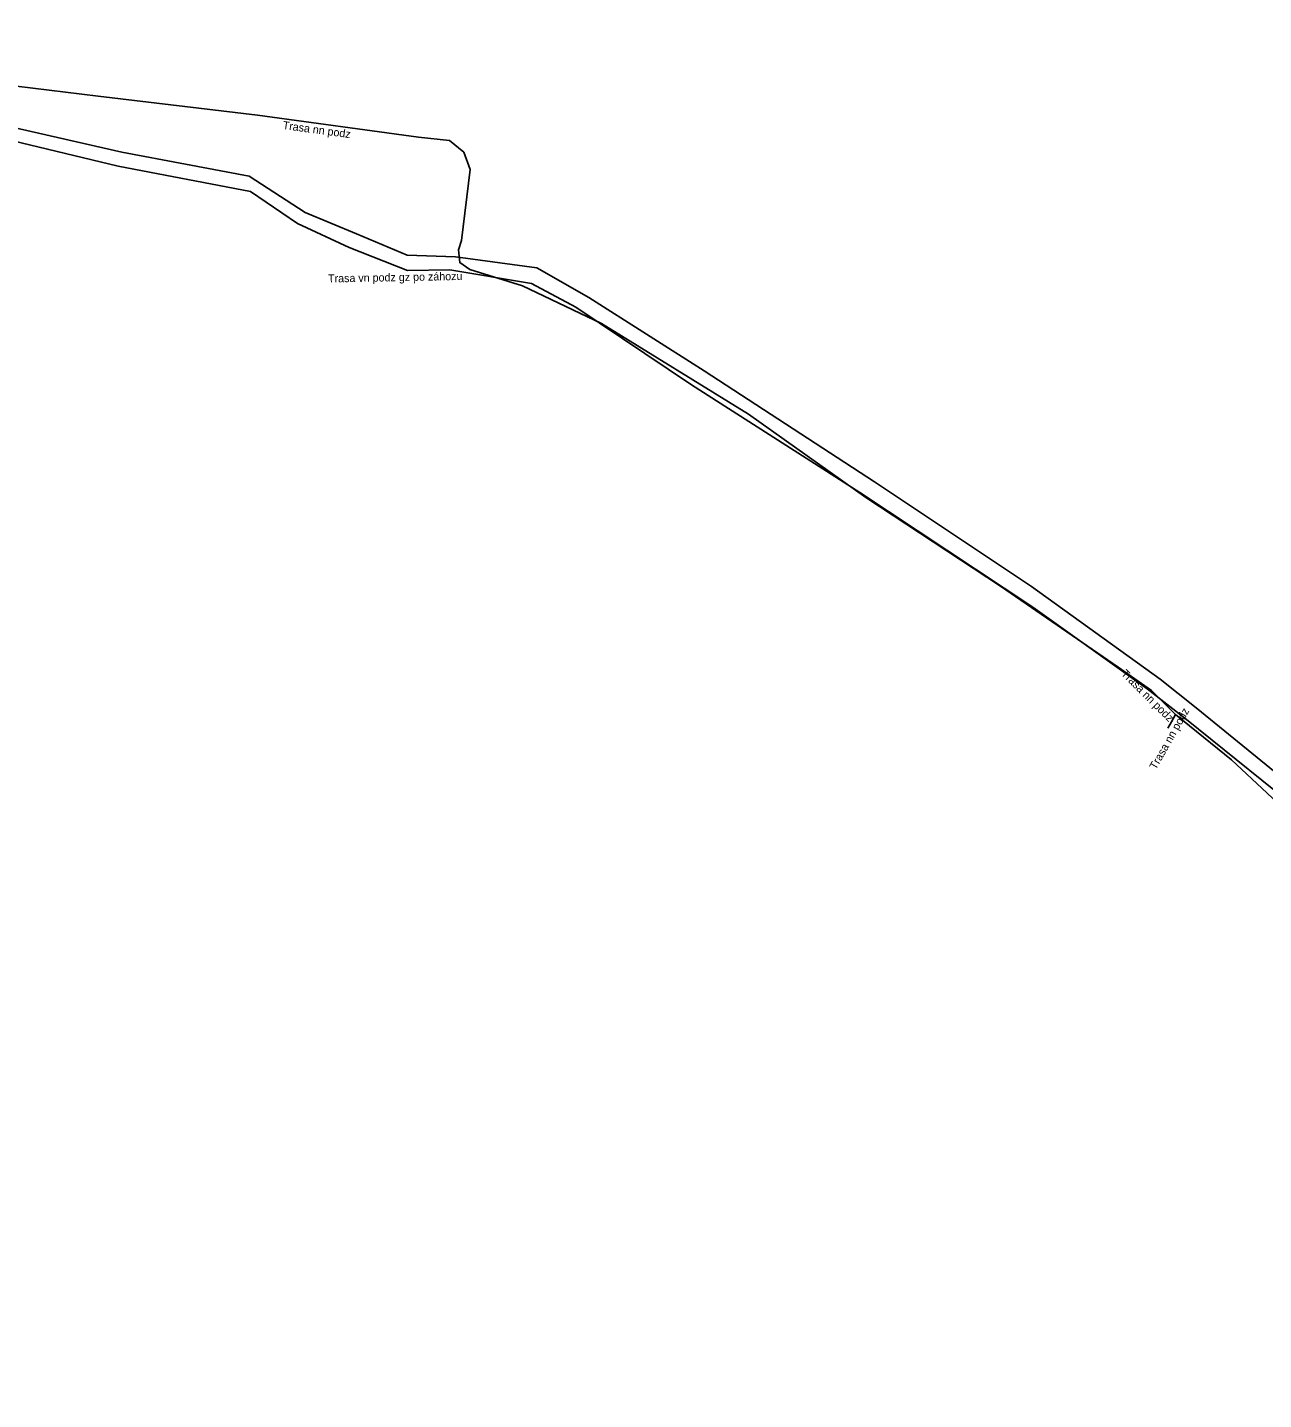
# Model space of a CAD drawing. Extents: x -651117 to -650186, y -983707 to -983198.
# Drawn here: x -650484.5 to -650407.2, y -983616.7 to -983530.9 of the extents above; entities that cross this region are included whole.
import ezdxf

# ---------------------------------------------------------------- set-up
doc = ezdxf.new("R2010")
doc.units = 0
for name, color, linetype in [('Popiskový text - Ostatní atributy Trasy', 7, 'Continuous'), ('Spojnice NN', 7, 'Continuous'), ('Spojnice VN', 7, 'Continuous')]:
    doc.layers.add(name, color=color, linetype=linetype)

msp = doc.modelspace()

# ---------------------------------------------------------------- linework, layer by layer
at = {"layer": 'Spojnice NN'}
for points in [[(-650490.27, -983533.98), (-650480.03, -983535.23), (-650470.09, -983536.41), (-650460.03, -983537.79), (-650458.09, -983538), (-650457.2, -983538.74), (-650456.8, -983539.82), (-650457.33, -983544.25), (-650457.52, -983544.84), (-650457.45, -983545.63), (-650456.81, -983546.06), (-650453.53, -983547.09), (-650448.59, -983549.43), (-650439.41, -983555.1), (-650432.08, -983560.3), (-650423.66, -983565.85), (-650416.32, -983570.9), (-650414.23, -983572.36)], [(-650412.73, -983573.85), (-650414.23, -983572.36)], [(-650413.22, -983574.71), (-650412.99, -983574.31), (-650412.73, -983573.85)], [(-650412.73, -983573.85), (-650409.23, -983576.69), (-650400.33, -983585.01), (-650393.41, -983589.45), (-650385.2, -983593.85), (-650379.4, -983596.94), (-650371.43, -983600.6), (-650366.94, -983602.92), (-650359.87, -983605.96), (-650355.25, -983609.16), (-650347.99, -983612.18), (-650341.78, -983614.49), (-650338.65, -983616.38), (-650338.55, -983616.65)]]:
    msp.add_lwpolyline(points, dxfattribs=at)
at = {"layer": 'Spojnice VN'}
for points in [[(-650457.71, -983545.27), (-650460.74, -983545.17), (-650463.89, -983543.84), (-650467.11, -983542.5), (-650470.6, -983540.24), (-650478.55, -983538.73), (-650491.83, -983535.71), (-650499.04, -983534.18), (-650503.77, -983533.37), (-650506.09, -983533.71), (-650507.92, -983534.36), (-650514.14, -983533.55), (-650522.56, -983532.3), (-650526.97, -983531.67), (-650530.77, -983530.94)], [(-650531.03, -983532), (-650527.35, -983532.69), (-650523.17, -983533.27), (-650514.12, -983534.42), (-650507.79, -983535.11), (-650505.59, -983534.27), (-650504.15, -983534.07), (-650499.05, -983534.96), (-650490.93, -983536.69), (-650478.78, -983539.61), (-650470.52, -983541.19), (-650467.59, -983543.18), (-650464.35, -983544.68), (-650460.72, -983546.13), (-650458.07, -983546.08), (-650452.96, -983546.93), (-650450.19, -983548.41), (-650442.98, -983553.27), (-650432.46, -983559.98), (-650421.65, -983567.15), (-650414.5, -983572.25), (-650412.05, -983574.17), (-650404.23, -983580.46), (-650397.97, -983586.13)], [(-650403.59, -983579.83), (-650411.44, -983573.44), (-650413.69, -983571.64), (-650421.72, -983565.86), (-650431.53, -983559.33), (-650442.18, -983552.38), (-650449.39, -983547.8), (-650452.63, -983545.95), (-650457.71, -983545.27)]]:
    msp.add_lwpolyline(points, dxfattribs=at)

# ---------------------------------------------------------------- texts
at = {"layer": 'Popiskový text - Ostatní atributy Trasy'}
for s, rotation, p in [('Trasa nn podz', 352.18909, (-650468.531, -983537.28)), ('Trasa vn podz gz po záhozu', 1.08092, (-650465.673, -983546.873)), ('Trasa nn podz', 315.19162, (-650416.171, -983571.348)), ('Trasa nn podz', 60.52411, (-650413.956, -983577.341))]:
    msp.add_text(s, height=0.5, rotation=rotation, dxfattribs=at).set_placement(p)

doc.saveas('drawing.dxf')
